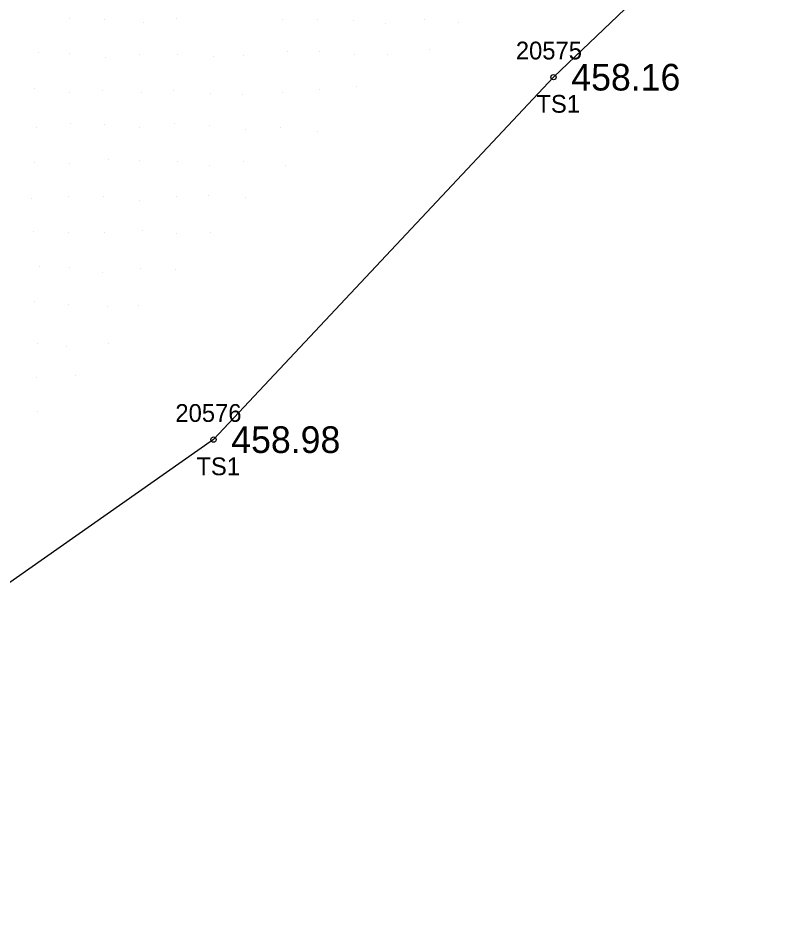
# Model space of a CAD drawing. Extents: x 1747760 to 1751131, y 649333 to 653784.
# Drawn here: x 1749281.6 to 1749323.7, y 651279.3 to 651329.8 of the extents above; entities that cross this region are included whole.
import ezdxf

# ---------------------------------------------------------------- set-up
doc = ezdxf.new("R2010")
doc.units = 0
for name, color, linetype in [('RD_DTM_BkLn2', 7, 'Continuous'), ('RD_DTM_BkLn_txCode', 7, 'Continuous'), ('RD_DTM_Spot', 7, 'Continuous'), ('RD_EX_TX_Misc_ELEV', 7, 'Continuous'), ('RD_SMD_Locator', 7, 'Continuous')]:
    doc.layers.add(name, color=color, linetype=linetype)

msp = doc.modelspace()

# ---------------------------------------------------------------- linework, layer by layer
at = {"layer": 'RD_DTM_BkLn2'}
msp.add_lwpolyline([(1749334.274, 651347.939), (1749311.737, 651326.42), (1749292.613, 651306.019), (1749271.131, 651290.935), (1749254.537, 651276.811), (1749242.73, 651265.483), (1749232.71, 651251.743), (1749211.561, 651228.743), (1749190.496, 651216.053), (1749178.766, 651203.369)], dxfattribs=at)
at = {"layer": 'RD_DTM_Spot'}
for p, q in [((1749284.507, 651329.743), (1749284.507, 651329.743)), ((1749286.489, 651329.664), (1749286.489, 651329.664)), ((1749288.663, 651329.49), (1749288.663, 651329.49)), ((1749290.514, 651329.729), (1749290.514, 651329.729)), ((1749296.52, 651329.693), (1749296.52, 651329.693)), ((1749298.472, 651329.693), (1749298.472, 651329.693)), ((1749300.495, 651329.631), (1749300.495, 651329.631)), ((1749302.302, 651329.449), (1749302.302, 651329.449)), ((1749304.497, 651329.685), (1749304.497, 651329.685)), ((1749306.392, 651329.498), (1749306.392, 651329.498)), ((1749296.748, 651327.868), (1749296.748, 651327.868)), ((1749298.59, 651327.868), (1749298.59, 651327.868)), ((1749304.775, 651327.983), (1749304.775, 651327.983)), ((1749282.768, 651327.791), (1749282.768, 651327.791)), ((1749284.507, 651327.733), (1749284.507, 651327.733)), ((1749286.547, 651327.542), (1749286.547, 651327.542)), ((1749288.477, 651327.712), (1749288.477, 651327.712)), ((1749290.572, 651327.686), (1749290.572, 651327.686)), ((1749292.598, 651327.583), (1749292.598, 651327.583)), ((1749294.28, 651327.643), (1749294.28, 651327.643)), ((1749300.56, 651327.696), (1749300.56, 651327.696)), ((1749302.421, 651327.678), (1749302.421, 651327.678)), ((1749282.538, 651325.782), (1749282.538, 651325.782)), ((1749300.669, 651325.886), (1749300.669, 651325.886)), ((1749284.536, 651325.533), (1749284.536, 651325.533)), ((1749286.349, 651325.649), (1749286.349, 651325.649)), ((1749288.538, 651325.54), (1749288.538, 651325.54)), ((1749290.371, 651325.684), (1749290.371, 651325.684)), ((1749292.464, 651325.526), (1749292.464, 651325.526)), ((1749294.267, 651325.419), (1749294.267, 651325.419)), ((1749296.5, 651325.57), (1749296.5, 651325.57)), ((1749298.554, 651325.737), (1749298.554, 651325.737)), ((1749284.586, 651323.797), (1749284.586, 651323.797)), ((1749290.447, 651323.816), (1749290.447, 651323.816)), ((1749282.684, 651323.583), (1749282.684, 651323.583)), ((1749286.471, 651323.736), (1749286.471, 651323.736)), ((1749288.459, 651323.572), (1749288.459, 651323.572)), ((1749292.4, 651323.7), (1749292.4, 651323.7)), ((1749294.392, 651323.469), (1749294.392, 651323.469)), ((1749296.4, 651323.591), (1749296.4, 651323.591)), ((1749298.439, 651323.362), (1749298.439, 651323.362)), ((1749286.72, 651321.776), (1749286.72, 651321.776)), ((1749288.475, 651321.756), (1749288.475, 651321.756)), ((1749282.536, 651321.643), (1749282.536, 651321.643)), ((1749284.515, 651321.584), (1749284.515, 651321.584)), ((1749290.587, 651321.668), (1749290.587, 651321.668)), ((1749292.398, 651321.453), (1749292.398, 651321.453)), ((1749294.322, 651321.684), (1749294.322, 651321.684)), ((1749296.657, 651321.465), (1749296.657, 651321.465)), ((1749292.354, 651319.77), (1749292.354, 651319.77)), ((1749282.383, 651319.572), (1749282.383, 651319.572)), ((1749284.435, 651319.696), (1749284.435, 651319.696)), ((1749286.446, 651319.702), (1749286.446, 651319.702)), ((1749288.448, 651319.476), (1749288.448, 651319.476)), ((1749290.542, 651319.699), (1749290.542, 651319.699)), ((1749294.411, 651319.654), (1749294.411, 651319.654)), ((1749282.477, 651317.739), (1749282.477, 651317.739)), ((1749288.614, 651317.767), (1749288.614, 651317.767)), ((1749284.47, 651317.683), (1749284.47, 651317.683)), ((1749286.477, 651317.682), (1749286.477, 651317.682)), ((1749290.514, 651317.597), (1749290.514, 651317.597)), ((1749292.461, 651317.679), (1749292.461, 651317.679)), ((1749282.854, 651315.773), (1749282.854, 651315.773)), ((1749284.493, 651315.683), (1749284.493, 651315.683)), ((1749286.373, 651315.422), (1749286.373, 651315.422)), ((1749288.48, 651315.629), (1749288.48, 651315.629)), ((1749290.456, 651315.585), (1749290.456, 651315.585)), ((1749282.556, 651313.82), (1749282.556, 651313.82)), ((1749284.449, 651313.629), (1749284.449, 651313.629)), ((1749286.677, 651313.522), (1749286.677, 651313.522)), ((1749288.409, 651313.583), (1749288.409, 651313.583)), ((1749282.723, 651311.408), (1749282.723, 651311.408)), ((1749284.327, 651311.251), (1749284.327, 651311.251)), ((1749286.702, 651311.416), (1749286.702, 651311.416)), ((1749284.85, 651309.652), (1749284.85, 651309.652)), ((1749282.648, 651309.497), (1749282.648, 651309.497)), ((1749282.703, 651307.591), (1749282.703, 651307.591))]:
    msp.add_line(p, q, dxfattribs=at)
at = {"layer": 'RD_SMD_Locator'}
for centre in [(1749311.737, 651326.42), (1749292.613, 651306.019)]:
    msp.add_circle(centre, 0.15, dxfattribs=at)

# ---------------------------------------------------------------- texts
at = {"layer": 'RD_DTM_BkLn_txCode'}
for s, p in [('20575', (1749309.619, 651327.42)), ('TS1', (1749310.776, 651324.42)), ('20576', (1749290.471, 651307.019)), ('TS1', (1749291.652, 651304.019))]:
    msp.add_text(s, height=1, dxfattribs=at).set_placement(p)
at = {"layer": 'RD_EX_TX_Misc_ELEV'}
for s, p in [('458.16', (1749312.737, 651325.67)), ('458.98', (1749293.613, 651305.269))]:
    msp.add_text(s, height=1.5, dxfattribs=at).set_placement(p)

doc.saveas('drawing.dxf')
